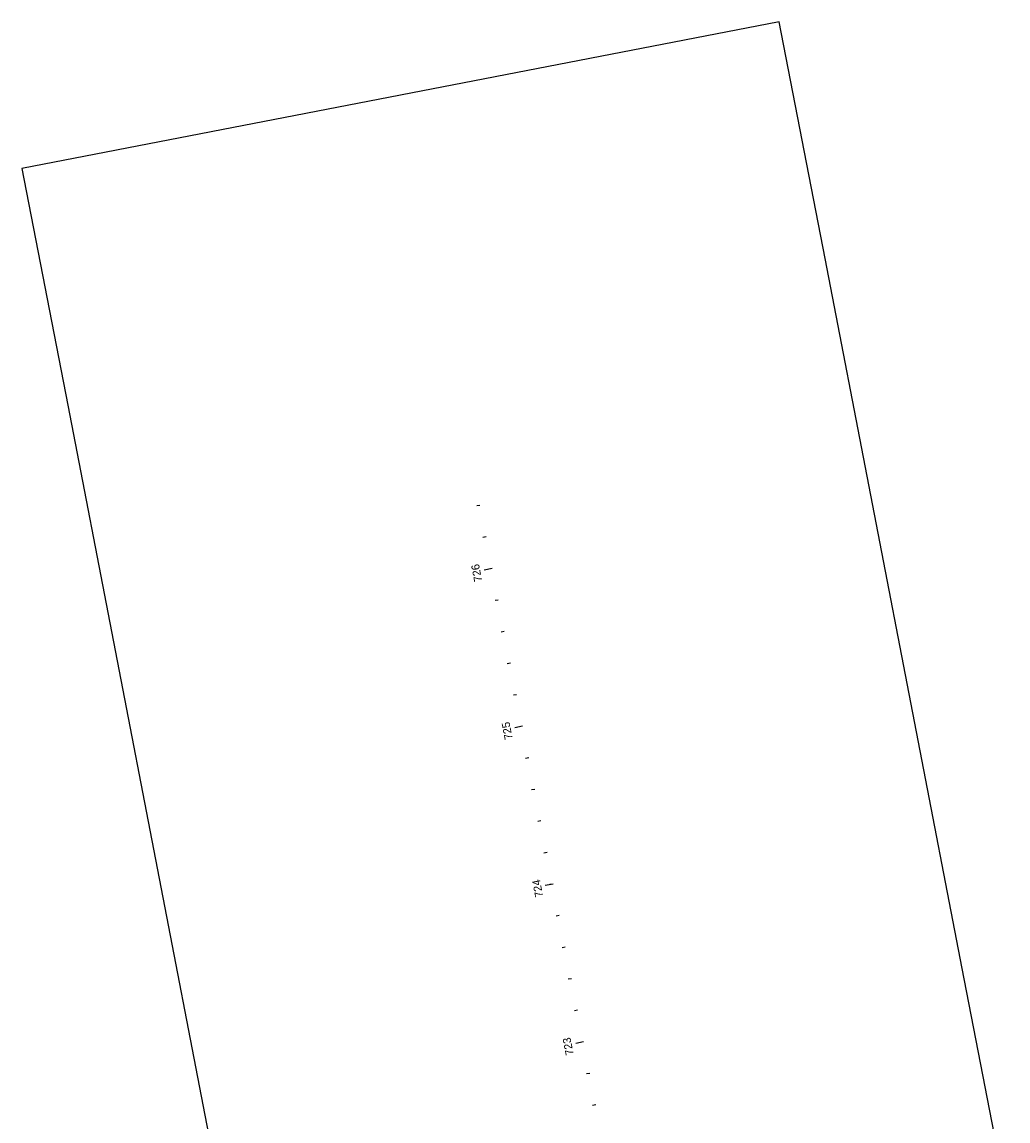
# Model space of a CAD drawing. Extents: x 2005381 to 2007040, y 402385 to 405116.
# Drawn here: x 2005381 to 2005994, y 404432 to 405116 of the extents above; entities that cross this region are included whole.
import ezdxf

# ---------------------------------------------------------------- set-up
doc = ezdxf.new("R2010")
doc.units = 0
for name, color, linetype in [('ClipDrawingBound_dp', 7, 'Continuous'), ('TextAlgnStation100', 7, 'Continuous'), ('TextAlgnStation500', 7, 'Continuous'), ('TextAlgnTicks100', 7, 'Continuous'), ('TextAlgnTicks1000', 7, 'Continuous'), ('TextAlgnTicks500', 7, 'Continuous')]:
    doc.layers.add(name, color=color, linetype=linetype)

msp = doc.modelspace()

# ---------------------------------------------------------------- linework, layer by layer
at = {"layer": 'ClipDrawingBound_dp'}
msp.add_lwpolyline([(2005522.84, 404288.61), (2005994.12, 404379.7), (2005965.66, 404526.97), (2005937.19, 404674.24), (2005908.73, 404821.52), (2005880.27, 404968.79), (2005851.8, 405116.07), (2005380.52, 405024.98), (2005408.99, 404877.71), (2005437.45, 404730.43), (2005465.92, 404583.16), (2005494.38, 404435.88)], close=True, dxfattribs=at)
at = {"layer": 'TextAlgnTicks100'}
for p, q in [((2005665.5, 404815.25), (2005663.54, 404814.87)), ((2005669.3, 404795.61), (2005667.33, 404795.23)), ((2005673.09, 404775.98), (2005668.18, 404775.03)), ((2005676.89, 404756.34), (2005674.92, 404755.96)), ((2005680.68, 404736.7), (2005678.72, 404736.32)), ((2005684.48, 404717.07), (2005682.51, 404716.69)), ((2005688.27, 404697.43), (2005686.31, 404697.05)), ((2005692.07, 404677.79), (2005687.16, 404676.84)), ((2005695.86, 404658.16), (2005693.9, 404657.78)), ((2005699.66, 404638.52), (2005697.69, 404638.14)), ((2005703.45, 404618.88), (2005701.49, 404618.5)), ((2005707.25, 404599.25), (2005705.28, 404598.87)), ((2005711.04, 404579.61), (2005706.13, 404578.66)), ((2005714.84, 404559.97), (2005712.88, 404559.59)), ((2005718.63, 404540.34), (2005716.67, 404539.96)), ((2005722.43, 404520.7), (2005720.47, 404520.32)), ((2005726.22, 404501.06), (2005724.26, 404500.68)), ((2005730.02, 404481.43), (2005725.11, 404480.48)), ((2005733.81, 404461.79), (2005731.85, 404461.41)), ((2005737.61, 404442.15), (2005735.65, 404441.77))]:
    msp.add_line(p, q, dxfattribs=at)
at = {"layer": 'TextAlgnTicks1000'}
for p, q in [((2005673.09, 404775.98), (2005671.13, 404775.6)), ((2005711.04, 404579.61), (2005709.08, 404579.23))]:
    msp.add_line(p, q, dxfattribs=at)
at = {"layer": 'TextAlgnTicks500'}
for p, q in [((2005673.09, 404775.98), (2005671.13, 404775.6)), ((2005692.07, 404677.79), (2005687.16, 404676.84)), ((2005711.04, 404579.61), (2005709.08, 404579.23)), ((2005730.02, 404481.43), (2005728.06, 404481.05))]:
    msp.add_line(p, q, dxfattribs=at)

# ---------------------------------------------------------------- texts
at = {"layer": 'TextAlgnStation100'}
for s, p in [('726', (2005666.96, 404768.16)), ('725', (2005685.94, 404669.95)), ('724', (2005704.91, 404571.84)), ('723', (2005723.9, 404473.56))]:
    msp.add_text(s, height=4.98, rotation=100.93889, dxfattribs=at).set_placement(p)
at = {"layer": 'TextAlgnStation500'}
msp.add_text('725', height=4.98, rotation=100.93889, dxfattribs=at).set_placement((2005685.94, 404669.95))

doc.saveas('drawing.dxf')
